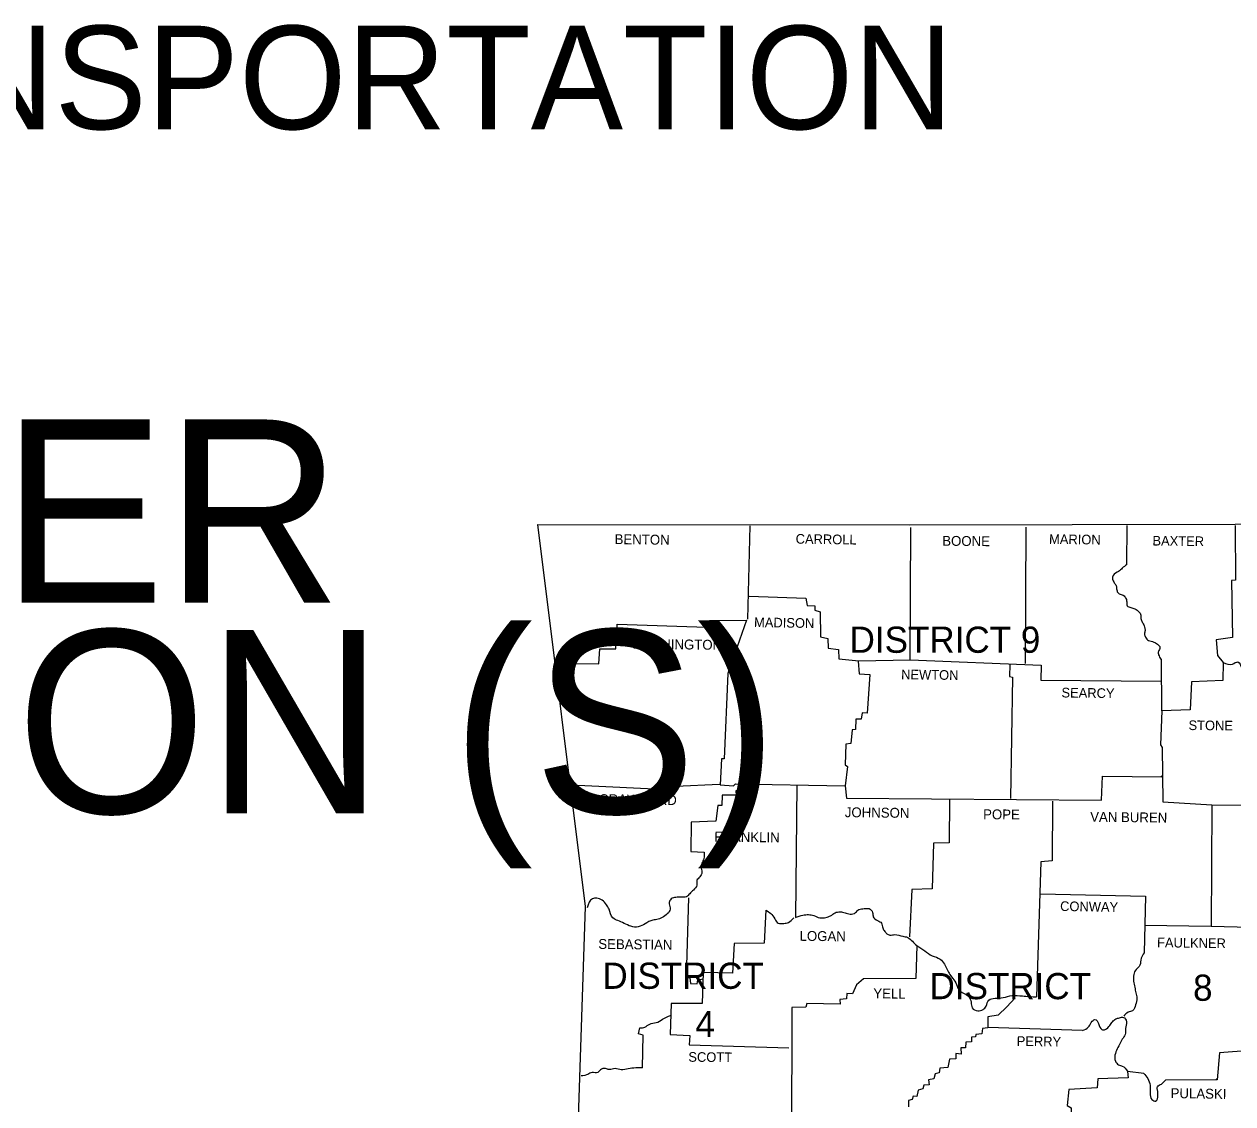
# Model space of a CAD drawing. Extents: x -549 to 3324, y -742 to 2142.
# Drawn here: x 2237 to 2752, y 1615 to 2074 of the extents above; entities that cross this region are included whole.
import ezdxf

# ---------------------------------------------------------------- set-up
doc = ezdxf.new("R2010")
doc.units = 0
for name, color, linetype in [('1', 7, 'Continuous'), ('2', 7, 'Continuous'), ('3', 7, 'Continuous')]:
    doc.layers.add(name, color=color, linetype=linetype)

msp = doc.modelspace()

# ---------------------------------------------------------------- linework, layer by layer
at = {"layer": '1'}
for points in [[(2455.88, 1861.21), (2614.09, 1861.12), (2752.92, 1861.41), (2916.71, 1863.95), (2992.63, 1865.72)], [(2455.88, 1861.21), (2476.13, 1698.6), (2467.33, 1433.16)], [(2546.19, 1860.63), (2545.3, 1821)], [(2545.99, 1830.69), (2570.06, 1829.91), (2570.65, 1826.77), (2573.97, 1826.68), (2573.87, 1824.72), (2576.22, 1824.13), (2576.42, 1813.47), (2579.45, 1812.78), (2579.65, 1808.58), (2583.95, 1807.99), (2584.15, 1804.08), (2592.66, 1803.2), (2614.58, 1803.68), (2614.77, 1859.94)], [(2663.79, 1860.14), (2663.5, 1802.02)], [(2706.84, 1860.82), (2706.64, 1844.09)], [(2752.92, 1860.82), (2753.12, 1837.54), (2751.45, 1837.44), (2751.75, 1813.08), (2744.9, 1812.1), (2745.49, 1805.54), (2747.83, 1802.51), (2747.64, 1794.78), (2734.33, 1794.29), (2733.84, 1782.36), (2721.71, 1781.96), (2721.12, 1767.48), (2721.81, 1766.31), (2722.1, 1743.22), (2743.04, 1741.85), (2742.75, 1690.29), (2759.38, 1689.8), (2759.38, 1637.36), (2746.27, 1636.38), (2745.29, 1624.83), (2723.28, 1624.73)], [(2463.61, 1802.02), (2481.9, 1801.92), (2482.39, 1808.38), (2489.14, 1808.38), (2489.73, 1818.85), (2527.89, 1817.48), (2529.06, 1820.42), (2544.82, 1820.51), (2536.89, 1797.81), (2535.32, 1761.52), (2534.15, 1761.42), (2533.56, 1750.46), (2539.34, 1749.97), (2540.22, 1750.85), (2586.89, 1749.97), (2587.38, 1744.78)], [(2592.46, 1803), (2592.86, 1797.72), (2597.36, 1797.42), (2596.18, 1780.99), (2594.13, 1781.08), (2593.74, 1778.44), (2591.39, 1778.44), (2591.29, 1773.94), (2589.82, 1773.84), (2589.33, 1768.07), (2587.18, 1767.78), (2586.89, 1758.97), (2587.87, 1758.29), (2586.89, 1749.97)], [(2614.58, 1803.68), (2670.34, 1801.34), (2670.25, 1794.98), (2721.42, 1794.59)], [(2656.94, 1801.63), (2656.84, 1796.54), (2658.11, 1796.25), (2657.33, 1744.59)], [(2721.71, 1781.96), (2721.61, 1803.98)], [(2470.07, 1750.36), (2514.58, 1748.31), (2514.78, 1749.87), (2533.37, 1750.75)], [(2566.34, 1750.36), (2565.66, 1693.91)], [(2587.38, 1744.78), (2695.98, 1743.9), (2696.47, 1754.18), (2721.71, 1753.88)], [(2721.42, 1753.98), (2721.71, 1754.27)], [(2542.17, 1749.58), (2542.17, 1747.82), (2540.31, 1747.82), (2540.41, 1746.06), (2534.44, 1745.96), (2534.35, 1741.56), (2532.68, 1741.56), (2531.8, 1735), (2521.24, 1734.51), (2521.14, 1722.09), (2526.81, 1721.69)], [(2631.31, 1744), (2631.21, 1725.71), (2624.46, 1725.61), (2623.87, 1706.14), (2615.26, 1705.84), (2614.28, 1685.69)], [(2675.14, 1743.51), (2674.94, 1718.07), (2670.25, 1717.68), (2668.39, 1660.15)], [(2743.04, 1741.85), (2793.33, 1741.56), (2797.64, 1743.61), (2797.34, 1705.35), (2794.41, 1704.08), (2791.77, 1701.83), (2790.88, 1700.95), (2790.79, 1689.99), (2758.79, 1689.99)], [(2670.05, 1704.08), (2714.76, 1703.01), (2714.18, 1678.84)], [(2520.16, 1702.32), (2519.18, 1668.66), (2520.65, 1668.27), (2520.94, 1665.92), (2523.88, 1665.73), (2524.17, 1667.39), (2526.52, 1667.78)], [(2553.03, 1697.04), (2552.35, 1683.05), (2539.63, 1682.95), (2538.94, 1670.23), (2526.32, 1670.52), (2525.93, 1657.41), (2512.72, 1657.31), (2512.33, 1644.2), (2520.65, 1643.71), (2520.36, 1639.7), (2562.82, 1638.53)], [(2714.28, 1690.68), (2742.75, 1690.29)], [(2617.32, 1682.07), (2616.92, 1667.98), (2594.62, 1667.88), (2591.68, 1665.34), (2590.02, 1661.42), (2587.57, 1661.62), (2587.47, 1659.37), (2584.64, 1659.08), (2584.73, 1657.02), (2570.55, 1657.41), (2570.06, 1655.85), (2564.19, 1655.65), (2563.99, 1598.41)], [(2659.29, 1659.76), (2655.77, 1655.95), (2651.95, 1652.32), (2647.55, 1651.64), (2647.55, 1647.04), (2645.4, 1646.75), (2645, 1644.4), (2642.56, 1644.2), (2642.36, 1643.13), (2640.7, 1643.03), (2640.6, 1640.98), (2638.25, 1640.88), (2638.06, 1638.53), (2636.1, 1638.53), (2636.2, 1635.79), (2634.05, 1635.99), (2633.95, 1633.83), (2631.31, 1633.64), (2630.52, 1630.12), (2627.2, 1629.82), (2626.9, 1627.86), (2625.14, 1627.38), (2624.65, 1625.32), (2622.4, 1624.83), (2622.6, 1622.78), (2620.35, 1622.58), (2619.96, 1621.02), (2617.9, 1620.43), (2617.41, 1617.79), (2615.85, 1617.88), (2615.36, 1616.52), (2613.89, 1616.03), (2613.79, 1613.38)], [(2687.96, 1645.87), (2647.65, 1647.14)], [(2500.49, 1630.02), (2500.79, 1643.81), (2498.83, 1644.4), (2499.42, 1647.04)], [(2714.08, 1627.57), (2707.04, 1628.35), (2707.33, 1625.71), (2694.51, 1625.22), (2694.12, 1621.41), (2682.09, 1620.72), (2681.4, 1613.87), (2683.16, 1612.99), (2683.16, 1608.49)], [(2744.8, 1624.93), (2745.29, 1625.42)]]:
    msp.add_lwpolyline(points, dxfattribs=at)
for points in [[(2706.64, 1844.09), (2704.88, 1842.63), (2703.32, 1841.26), (2700.97, 1839.59), (2700.68, 1838.03), (2701.46, 1836.46), (2702.24, 1835.19), (2702.53, 1833.43), (2703.22, 1831.96), (2704.88, 1831.37), (2706.25, 1830.1), (2706.74, 1828.34), (2706.94, 1826.68), (2708.5, 1825.89), (2710.26, 1825.31), (2711.93, 1824.13), (2712.71, 1822.67), (2712.91, 1820.81), (2713.59, 1819.34), (2714.37, 1817.58), (2714.57, 1816.11), (2714.37, 1814.64), (2714.76, 1813.27), (2716.04, 1811.9), (2718.29, 1811.22), (2719.85, 1810.24), (2720.93, 1808.87), (2720.24, 1807.21), (2720.34, 1805.74), (2721.22, 1803.98)], [(2747.83, 1802.51), (2751.75, 1801.83), (2754.1, 1802.71), (2755.76, 1800.16), (2756.64, 1798.21), (2758.11, 1795.37), (2760.46, 1794.49), (2762.22, 1792.92), (2762.22, 1791.26), (2760.65, 1789.69), (2759.48, 1788.13), (2759.87, 1786.27), (2760.26, 1783.72), (2760.26, 1781.28), (2759.67, 1779.03), (2759.18, 1776.97), (2759.67, 1775.21), (2761.53, 1775.51), (2763.49, 1776.97), (2765.54, 1776.97), (2767.5, 1775.9), (2769.56, 1774.04), (2771.61, 1774.43), (2773.27, 1774.92), (2775.62, 1775.6), (2777.28, 1774.72), (2778.75, 1773.55), (2780.51, 1771.69), (2782.18, 1770.52), (2784.33, 1769.44), (2786.97, 1768.76), (2789.42, 1767.09), (2789.81, 1764.25), (2789.71, 1761.81), (2789.51, 1758.78), (2789.32, 1755.45), (2789.61, 1752.22), (2790.69, 1750.07), (2792.06, 1747.52), (2792.45, 1745.18), (2792.35, 1741.46)], [(2526.81, 1721.69), (2526.81, 1719.64), (2526.03, 1717.49), (2525.54, 1715.63), (2525.83, 1713.18), (2524.95, 1711.22), (2523.68, 1709.66), (2523.68, 1707.7), (2522.21, 1705.65), (2520.65, 1704.08), (2519.28, 1702.81), (2516.83, 1702.62), (2514.78, 1702.52), (2512.72, 1701.83), (2511.94, 1700.36), (2512.33, 1698.11), (2511.55, 1695.96), (2509.49, 1694.3), (2507.24, 1693.22), (2504.9, 1692.83), (2501.67, 1691.27), (2498.73, 1689.99), (2495.6, 1690.19), (2492.67, 1691.46), (2490.02, 1692.64), (2487.97, 1693.81), (2486.31, 1697.43), (2485.23, 1699.39), (2483.37, 1701.34), (2481.12, 1702.13), (2479.26, 1701.93), (2477.01, 1698.11)], [(2553.03, 1697.04), (2555.19, 1695.67), (2556.85, 1693.42), (2558.32, 1691.56), (2560.76, 1691.46), (2562.72, 1691.85), (2564.97, 1693.81)], [(2565.66, 1693.91), (2568.88, 1694.98), (2571.23, 1695.18), (2573.58, 1694.79), (2576.03, 1693.81), (2578.67, 1694.01), (2580.63, 1694.69), (2582.58, 1695.96), (2584.73, 1696.35), (2586.79, 1695.96), (2588.94, 1695.37), (2591.29, 1696.06), (2592.66, 1697.33), (2595.01, 1697.72), (2597.06, 1697.72), (2598.53, 1696.06), (2598.82, 1694.3), (2600.68, 1692.64), (2602.35, 1691.56), (2602.83, 1689.5), (2603.72, 1688.04), (2604.6, 1687.06), (2605.87, 1686.47), (2608.02, 1686.67), (2611.35, 1685.98), (2613.5, 1685.49), (2615.46, 1683.83), (2617.32, 1682.07)], [(2617.32, 1682.07), (2620.74, 1679.72), (2623.97, 1677.67), (2627.3, 1676.2), (2629.15, 1674.05), (2630.82, 1670.72), (2632.19, 1668.66), (2633.95, 1666.12), (2635.22, 1663.28), (2637.27, 1661.72), (2639.43, 1660.35), (2640.5, 1657.9), (2640.99, 1655.46), (2643.34, 1654.28), (2645.59, 1654.77), (2646.86, 1656.24), (2648.04, 1658.78), (2650.68, 1659.57), (2654.1, 1659.86), (2658.02, 1660.74), (2662.32, 1660.54), (2668.39, 1660.15)], [(2714.18, 1678.84), (2712.91, 1676.59), (2712.32, 1673.65), (2710.75, 1671.8), (2709.77, 1669.64), (2709.68, 1666.81), (2710.17, 1664.26), (2710.66, 1661.82), (2711.05, 1659.57), (2710.56, 1656.73), (2709.29, 1654.28), (2707.33, 1653.6), (2705.47, 1651.93)], [(2499.42, 1647.04), (2501.57, 1647.24), (2503.62, 1648.61), (2506.36, 1649.19), (2509.1, 1650.66), (2512.53, 1652.23)], [(2687.96, 1645.87), (2690.4, 1647.24), (2691.67, 1649.29), (2693.24, 1650.56), (2694.81, 1648.8), (2696.17, 1646.26), (2697.64, 1646.26), (2699.5, 1648.02), (2700.68, 1649.59), (2702.14, 1650.76), (2703.71, 1651.25), (2705.37, 1651.44), (2706.64, 1649.59), (2706.25, 1646.65), (2706.25, 1644.69), (2705.18, 1642.64), (2704, 1640.49), (2702.73, 1638.04), (2701.75, 1635.4), (2701.95, 1632.85), (2703.32, 1631.19), (2704.88, 1630.7), (2707.04, 1628.55)], [(2500.49, 1630.02), (2497.66, 1629.92), (2494.43, 1629.53), (2491.49, 1629.14), (2488.85, 1629.63), (2486.4, 1629.23), (2484.74, 1629.63), (2482.69, 1629.14), (2481.51, 1627.96), (2479.07, 1627.96), (2477.31, 1627.18), (2474.47, 1626.49)], [(2714.08, 1627.57), (2715.74, 1625.42), (2716.72, 1622.48), (2716.72, 1619.16), (2717.5, 1616.42), (2719.07, 1615.83), (2720.05, 1618.18), (2719.85, 1620.53), (2719.85, 1621.9), (2721.52, 1623.07), (2723.28, 1624.73)]]:
    msp.add_spline(points, degree=3, dxfattribs=at)

# ---------------------------------------------------------------- texts
at = {"layer": '2'}
for s, height, p in [('ARKANSAS DEPARTMENT OF TRANSPORTATION', 44.0283, (1232.79, 2029.52)), ('ELEVEN POINT RIVER ', 78, (1265.44, 1827.97)), ('STREAM RESTORATION (S)', 78, (1173.32, 1738.3))]:
    msp.add_text(s, height=height, dxfattribs=at).set_placement(p)
for s, height, rotation, p in [('BENTON', 4.207, 359.2527, (2488.65, 1852.9)), ('CARROLL', 4.109, 359.1481, (2565.75, 1853.09)), ('BOONE', 4.207, 359.4001, (2628.18, 1852.21)), ('MARION', 4.109, 359.1854, (2673.67, 1853)), ('BAXTER', 4.109, 359.2559, (2717.7, 1852.31)), ('MADISON', 4.109, 359.0906, (2548.04, 1817.58)), ('WASHINGTON', 4.206, 359.232, (2495.7, 1808.38)), ('NEWTON', 4.109, 359.2717, (2610.66, 1795.37)), ('SEARCY', 4.108, 359.2527, (2678.95, 1787.64)), ('STONE', 4.108, 359.4001, (2733.06, 1773.75)), ('CRAWFORD', 4.206, 359.2771, (2482, 1742.24)), ('JOHNSON', 4.207, 359.3514, (2586.69, 1736.66)), ('POPE', 4.207, 359.6155, (2645.59, 1735.78)), ('VAN BUREN', 4.207, 359.3508, (2691.18, 1734.71)), ('FRANKLIN', 4.207, 359.1815, (2531.12, 1726.29)), ('CONWAY', 4.108, 359.0371, (2678.37, 1696.74)), ('SEBASTIAN', 4.206, 359.2816, (2481.71, 1680.6)), ('LOGAN', 4.207, 359.3969, (2567.42, 1684.03)), ('FAULKNER', 4.109, 359.2486, (2719.66, 1681.29)), ('YELL', 4.207, 359.1987, (2598.82, 1659.57)), ('PERRY', 4.109, 359.0858, (2659.88, 1639.31)), ('SCOTT', 4.109, 359.4063, (2520.06, 1632.56)), ('PULASKI', 4.207, 359.053, (2725.43, 1617.1))]:
    msp.add_text(s, height=height, rotation=rotation, dxfattribs=at).set_placement(p)
at = {"layer": '3'}
for s, height, p in [('DISTRICT 9', 11.154, (2588.75, 1806.62)), ('DISTRICT', 11.154, (2483.47, 1663.58)), ('DISTRICT', 11.154, (2622.79, 1659.17)), ('8', 11.15, (2735.02, 1658.49)), ('4', 11.15, (2523.09, 1643.03))]:
    msp.add_text(s, height=height, dxfattribs=at).set_placement(p)

doc.saveas('drawing.dxf')
